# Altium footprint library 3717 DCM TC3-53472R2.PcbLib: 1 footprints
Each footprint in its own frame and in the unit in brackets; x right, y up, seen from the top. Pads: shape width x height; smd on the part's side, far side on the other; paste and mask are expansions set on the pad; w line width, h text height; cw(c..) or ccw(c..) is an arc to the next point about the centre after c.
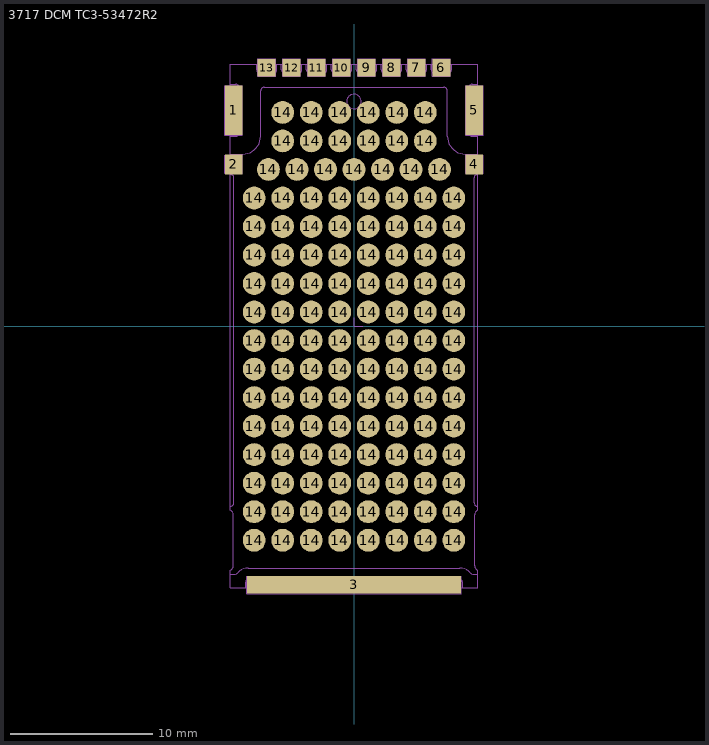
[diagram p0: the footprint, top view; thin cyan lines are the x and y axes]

## 3717 DCM TC3-53472R2 [mm] "PRODUCT OUTLINE 3717 DCM TC3-53472R2"
pads (136):
  rect 1.23x3.47 smd mask-0.05: 1(-8.445,15.14) 5(8.445,15.14)
  rect 1.23x1.38 smd mask-0.05: 2(-8.445,11.35)
  rect 15.04x1.23 smd mask-0.05: 3(0,-18.135)
  rect 1.231x1.38 smd mask-0.05: 4(8.445,11.35)
  rect 1.245x1.23 smd mask-0.05: 6(6.13,18.135) 7(4.38,18.135) 8(2.63,18.135) 9(0.88,18.135) 10(-0.88,18.135) 11(-2.63,18.135) 12(-4.38,18.135) 13(-6.13,18.135)
  round 1.6 smd mask-0.05: 14(-7,-15) 14(-7,-13) 14(-7,-11) 14(-7,-9) 14(-7,-7) 14(-7,-5) 14(-7,-3) 14(-7,-1) 14(-7,1) 14(-7,3) 14(-7,5) 14(-7,7) 14(-7,9) 14(-6,11) 14(-5,-15) 14(-5,-13) 14(-5,-11) 14(-5,-9) 14(-5,-7) 14(-5,-5) 14(-5,-3) 14(-5,-1) 14(-5,1) 14(-5,3) 14(-5,5) 14(-5,7) 14(-5,9) 14(-5,13) 14(-5,15) 14(-4,11) 14(-3,-15) 14(-3,-13) 14(-3,-11) 14(-3,-9) 14(-3,-7) 14(-3,-5) 14(-3,-3) 14(-3,-1) 14(-3,1) 14(-3,3) 14(-3,5) 14(-3,7) 14(-3,9) 14(-3,13) 14(-3,15) 14(-2,11) 14(-1,-15) 14(-1,-13) 14(-1,-11) 14(-1,-9) 14(-1,-7) 14(-1,-5) 14(-1,-3) 14(-1,-1) 14(-1,1) 14(-1,3) 14(-1,5) 14(-1,7) 14(-1,9) 14(-1,13) 14(-1,15) 14(0,11) 14(1,-15) 14(1,-13) 14(1,-11) 14(1,-9) 14(1,-7) 14(1,-5) 14(1,-3) 14(1,-1) 14(1,1) 14(1,3) 14(1,5) 14(1,7) 14(1,9) 14(1,13) 14(1,15) 14(2,11) 14(3,-15) 14(3,-13) 14(3,-11) 14(3,-9) 14(3,-7) 14(3,-5) 14(3,-3) 14(3,-1) 14(3,1) 14(3,3) 14(3,5) 14(3,7) 14(3,9) 14(3,13) 14(3,15) 14(4,11) 14(5,-15) 14(5,-13) 14(5,-11) 14(5,-9) 14(5,-7) 14(5,-5) 14(5,-3) 14(5,-1) 14(5,1) 14(5,3) 14(5,5) 14(5,7) 14(5,9) 14(5,13) 14(5,15) 14(6,11) 14(7,-15) 14(7,-13) 14(7,-11) 14(7,-9) 14(7,-7) 14(7,-5) 14(7,-3) 14(7,-1) 14(7,1) 14(7,3) 14(7,5) 14(7,7) 14(7,9)
Mechanical 1:
  lines w0.012: 0,0.6 0,0 0.6,0
Mechanical 8:
  drawing of 204 lines, arcs and shapes, not listed
3D body: height 0, standoff 0, extent -8.668,-18.345 8.669,18.365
